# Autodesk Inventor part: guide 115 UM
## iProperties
Shininess: 33.0
Angle Display Precision: 2
Document Length Units: 11269
Document Angle Units: 11279
Document Time Units: 11290
Document Mass Units: 11283
Document Length Units Precision: 3
Document Angle Units Precision: 2
Part Number: guide 115 UM
Material: Par défaut
Document SubType Name: Modeling
Density: 0.0
Volumn: 0.0
Area: 0.0
PropertySet Name: Model Information
Control State: 0
Master: False
Checked Out: False
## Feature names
1. Extrusion1
2. Chanfrein1 [Chamfer]
3. Perçage1 [Hole]
4. Perçage2 [Hole]
